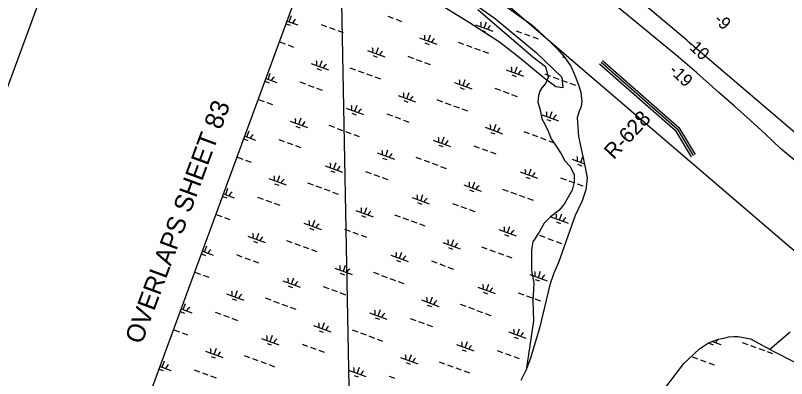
# Model space of a CAD drawing. Extents: x 3972907 to 3994831, y 172639 to 190852.
# Drawn here: x 3977932 to 3980022, y 187328 to 188313 of the extents above; entities that cross this region are included whole.
import ezdxf

# ---------------------------------------------------------------- set-up
doc = ezdxf.new("R2010")
doc.units = 0
for name, color, linetype in [('V-ANNO-SYMB', 7, 'Continuous'), ('V-ANNO-TEXT', 7, 'Continuous'), ('V-GRID-FRAM', 7, 'Continuous'), ('V-GRID-MAJR', 7, 'Continuous'), ('V-RIVR-EDGE', 7, 'Continuous'), ('V-RIVR-JETY', 7, 'Continuous'), ('V-RIVR-RANG', 7, 'Continuous'), ('V-RIVR-RANG-IDEN', 7, 'Continuous'), ('V-SITE-VEGE', 7, 'Continuous'), ('V-TOPO-DPTH', 7, 'Continuous'), ('V-TOPO-MINR', 7, 'Continuous'), ('V-WETL-SWMP', 7, 'Continuous')]:
    doc.layers.add(name, color=color, linetype=linetype)

msp = doc.modelspace()

# ---------------------------------------------------------------- linework, layer by layer
at = {"layer": 'V-ANNO-SYMB'}
msp.add_lwpolyline([(3974579.2, 179056.1), (3990105.3, 173349.5), (3994058.3, 184104.4), (3978532.2, 189811), (3974579.2, 179056.1)], dxfattribs=at)
at = {"layer": 'V-GRID-FRAM'}
msp.add_lwpolyline([(3976065.4, 181215.5), (3978987, 189164.4), (3993292.9, 183906.2), (3990371.3, 175957.4), (3976065.4, 181215.5)], dxfattribs=at)
at = {"layer": 'V-GRID-MAJR'}
msp.add_spline([(3978982.9, 179660), (3978930.1, 182429.9), (3978814.7, 188489.8), (3978791.3, 189715.7)], degree=3, dxfattribs=at)
at = {"layer": 'V-RIVR-EDGE'}
for points in [[(3979185.5, 188329.4), (3979205.2, 188311.9), (3979335.1, 188200.5), (3979369, 188174.3), (3979376.6, 188144.8), (3979369, 188128.4), (3979359.1, 188116.4), (3979353.7, 188107.7), (3979350.4, 188095.7), (3979348.2, 188078.2), (3979354.8, 188057.5), (3979359.1, 188032.3), (3979367.9, 188016), (3979376.6, 187999.6), (3979384.3, 187978.8), (3979399.6, 187955.9), (3979411.6, 187937.3), (3979421.4, 187918.8), (3979435.6, 187903.5), (3979446.5, 187880.5), (3979446.5, 187860.9), (3979441.1, 187839), (3979419.2, 187800.8), (3979405, 187784.4), (3979382.1, 187766.9), (3979365.7, 187749.5), (3979351.5, 187725.4), (3979335.1, 187699.2), (3979330.8, 187677.4), (3979330.8, 187621.7), (3979337.3, 187586.7), (3979335.1, 187538.7), (3979336.2, 187485.2), (3979316.2, 187350.6)], [(3979977.1, 187407.6), (3980031.9, 187455.1)]]:
    msp.add_lwpolyline(points, dxfattribs=at)
at = {"layer": 'V-RIVR-JETY'}
for points in [[(3979523.8, 188191.1), (3979730.4, 188009.6), (3979774.3, 187936)], [(3979515.5, 188181.7), (3979720.6, 188001.5), (3979763.5, 187929.6)], [(3979519.6, 188186.4), (3979725.5, 188005.6), (3979768.9, 187932.8)]]:
    msp.add_lwpolyline(points, dxfattribs=at)
msp.add_spline([(3979098.2, 189603), (3979284.7, 189431.5), (3979614.8, 189124.3), (3979920, 188846.7), (3980228.2, 188557.9), (3980477.4, 188312.8), (3980532, 188268.2), (3980570.9, 188243.1), (3980628.8, 188186.6), (3980663.7, 188142.5)], degree=3, dxfattribs=at)
at = {"layer": 'V-SITE-VEGE'}
for p, q in [((3979149.6, 188364.2), (3979233.9, 188303.6)), ((3979162.7, 188293), (3979073.2, 188348.4)), ((3979244.4, 188240.3), (3979162.7, 188293)), ((3979233.9, 188303.6), (3979344.5, 188211.3)), ((3979302.3, 188195.5), (3979244.4, 188240.3)), ((3979344.5, 188211.3), (3979413, 188145.4)), ((3979365.5, 188142.8), (3979302.3, 188195.5)), ((3979397.2, 188119.1), (3979365.5, 188142.8)), ((3979413, 188145.4), (3979415.6, 188116.5)), ((3979415.6, 188116.5), (3979397.2, 188119.1))]:
    msp.add_line(p, q, dxfattribs=at)
at = {"layer": 'V-TOPO-DPTH'}
for points in [[(3980186.5, 187874.7), (3979782.7, 188218.5), (3979779.2, 188221.6), (3979778, 188222.6), (3979770.9, 188228.8), (3979766.2, 188233), (3979761.5, 188237.2), (3979756.8, 188241.4), (3979752.2, 188245.7), (3979157.5, 188744)], [(3978990.6, 188578.5), (3980546.8, 187243.1), (3981084.2, 186920)]]:
    msp.add_lwpolyline(points, dxfattribs=at)
at = {"layer": 'V-TOPO-MINR'}
for points in [[(3980186.5, 187874.7), (3979782.7, 188218.5), (3979779.2, 188221.6), (3979778, 188222.6), (3979770.9, 188228.8), (3979766.2, 188233), (3979761.5, 188237.2), (3979756.8, 188241.4), (3979752.2, 188245.7), (3979157.5, 188744)], [(3980399.4, 187625), (3980006.3, 187952.1), (3979965, 187990.7), (3979923.4, 188029), (3979881.4, 188066.9), (3979839.2, 188104.5), (3979779.4, 188157.2), (3979766.8, 188168.2), (3979754.1, 188179.2), (3979741.4, 188190), (3979728.5, 188200.7), (3979422.8, 188453.3)]]:
    msp.add_lwpolyline(points, dxfattribs=at)
at = {"layer": 'V-WETL-SWMP'}
for p, q in [((3979255.7, 188341.9), (3979310.5, 188303.1)), ((3978668.6, 188297.9), (3978697.8, 188287.2)), ((3978674.3, 188295.8), (3978680.5, 188312.7)), ((3978941.5, 188310.9), (3978956.5, 188305.4)), ((3978964, 188302.6), (3978979, 188297.1)), ((3979202.8, 188278.8), (3979209, 188295.7)), ((3979310.5, 188303.1), (3979331.9, 188287.5)), ((3978666, 188290.7), (3978677.3, 188286.5)), ((3978760.7, 188288.8), (3978775.8, 188283.3)), ((3978783.3, 188280.5), (3978798.3, 188275)), ((3978805.8, 188272.2), (3978820.8, 188266.7)), ((3979179.3, 188287.4), (3979226.3, 188270.2)), ((3979194.5, 188273.6), (3979205.8, 188269.5)), ((3979331.9, 188287.5), (3979349.2, 188272.4)), ((3979349.2, 188272.4), (3979366.5, 188256)), ((3979027.2, 188252.4), (3979074.1, 188235.1)), ((3979050.6, 188243.7), (3979056.9, 188260.6)), ((3979289.2, 188271.8), (3979304.2, 188266.3)), ((3979311.7, 188263.5), (3979326.8, 188258)), ((3979334.3, 188255.2), (3979349.3, 188249.7)), ((3979366.5, 188256), (3979382.5, 188240.5)), ((3978648.5, 188241.3), (3978663.5, 188235.8)), ((3978671.1, 188233.1), (3978686.1, 188227.5)), ((3979042.4, 188238.6), (3979053.6, 188234.4)), ((3979132, 188240.9), (3979147, 188235.4)), ((3979154.5, 188232.6), (3979169.5, 188227.1)), ((3979382.5, 188240.5), (3979401.4, 188221.2)), ((3978886.4, 188217.9), (3978933.3, 188200.6)), ((3978909.9, 188209.3), (3978916.1, 188226.1)), ((3979177, 188224.3), (3979192, 188218.8)), ((3979199.5, 188216), (3979214.5, 188210.5)), ((3979401.4, 188221.2), (3979420.3, 188199.8)), ((3978757.7, 188174.2), (3978763.9, 188191.1)), ((3978901.6, 188204.1), (3978912.8, 188199.9)), ((3978996.3, 188202.2), (3979011.3, 188196.7)), ((3979018.8, 188193.9), (3979033.8, 188188.4)), ((3979414.9, 188200.9), (3979421.1, 188198.6)), ((3979420.3, 188199.8), (3979437.4, 188175.5)), ((3978734.3, 188182.8), (3978781.2, 188165.6)), ((3978749.4, 188169), (3978760.7, 188164.9)), ((3978839, 188171.3), (3978854, 188165.8)), ((3979041.3, 188185.7), (3979056.4, 188180.1)), ((3979286.2, 188157.2), (3979292.4, 188174.1)), ((3979437.4, 188175.5), (3979450.4, 188146.3)), ((3978616.9, 188139.7), (3978623.2, 188156.6)), ((3978861.5, 188163.1), (3978876.6, 188157.5)), ((3978884.1, 188154.8), (3978899.1, 188149.3)), ((3978906.6, 188146.5), (3978921.6, 188141)), ((3979262.7, 188165.8), (3979309.7, 188148.5)), ((3979277.9, 188152), (3979289.2, 188147.8)), ((3979367.5, 188154.3), (3979382.5, 188148.8)), ((3978608.6, 188134.5), (3978619.9, 188130.4)), ((3978611.2, 188141.8), (3978640.4, 188131.1)), ((3978703.4, 188132.7), (3978718.4, 188127.2)), ((3979122, 188131.3), (3979168.9, 188114.1)), ((3979145.4, 188122.7), (3979151.6, 188139.6)), ((3979390, 188146), (3979405, 188140.5)), ((3979412.6, 188137.7), (3979427.6, 188132.2)), ((3979435.1, 188129.5), (3979450.1, 188123.9)), ((3979450.4, 188146.3), (3979460.1, 188119.6)), ((3978725.9, 188124.4), (3978740.9, 188118.9)), ((3978748.4, 188116.1), (3978763.4, 188110.6)), ((3979137.1, 188117.5), (3979148.4, 188113.4)), ((3979231.8, 188115.6), (3979246.9, 188110.1)), ((3979254.4, 188107.4), (3979269.4, 188101.8)), ((3979460.1, 188119.6), (3979464.9, 188104.2)), ((3978591.1, 188085.2), (3978606.2, 188079.7)), ((3978969.8, 188096.2), (3979016.7, 188079)), ((3978993.3, 188087.6), (3978999.5, 188104.5)), ((3979074.6, 188084.8), (3979089.6, 188079.2)), ((3979276.9, 188099.1), (3979291.9, 188093.6)), ((3979464.9, 188104.2), (3979467.5, 188080.1)), ((3978613.7, 188076.9), (3978628.7, 188071.4)), ((3978852.5, 188053.1), (3978858.7, 188070)), ((3978985, 188082.4), (3978996.2, 188078.3)), ((3979097.1, 188076.5), (3979112.1, 188071)), ((3979119.6, 188068.2), (3979134.6, 188062.7)), ((3979465.3, 188066), (3979459.3, 188050.7)), ((3979467.5, 188080.1), (3979465.3, 188066)), ((3978829, 188061.8), (3978876, 188044.5)), ((3978844.2, 188048), (3978855.5, 188043.8)), ((3978938.9, 188046.1), (3978953.9, 188040.6)), ((3979142.1, 188059.9), (3979157.2, 188054.4)), ((3979357.5, 188044.7), (3979404.4, 188027.5)), ((3979381, 188036.1), (3979387.2, 188053)), ((3979459.3, 188050.7), (3979455, 188035.8)), ((3978676.9, 188026.7), (3978723.8, 188009.4)), ((3978700.3, 188018.1), (3978706.5, 188035)), ((3978961.4, 188037.8), (3978976.4, 188032.3)), ((3978984, 188029.5), (3978999, 188024)), ((3979372.7, 188030.9), (3979383.9, 188026.8)), ((3979455, 188035.8), (3979458.6, 187985.1)), ((3978559.6, 187983.6), (3978565.8, 188000.5)), ((3978692, 188012.9), (3978703.3, 188008.7)), ((3978781.6, 188015.2), (3978796.7, 188009.7)), ((3978804.2, 188006.9), (3978819.2, 188001.4)), ((3979205.3, 188009.7), (3979252.3, 187992.4)), ((3979228.8, 188001), (3979235, 188017.9)), ((3978553.8, 187985.7), (3978583, 187975)), ((3978826.7, 187998.6), (3978841.7, 187993.1)), ((3978849.2, 187990.4), (3978864.2, 187984.8)), ((3979088, 187966.6), (3979094.2, 187983.4)), ((3979220.5, 187995.9), (3979231.8, 187991.7)), ((3979310.1, 187998.2), (3979325.1, 187992.7)), ((3979332.6, 187989.9), (3979347.7, 187984.4)), ((3979355.2, 187981.6), (3979370.2, 187976.1)), ((3979458.6, 187985.1), (3979474.8, 187909.4)), ((3978551.3, 187978.4), (3978562.5, 187974.3)), ((3978646, 187976.5), (3978661, 187971)), ((3978668.5, 187968.3), (3978683.5, 187962.7)), ((3978691, 187960), (3978706, 187954.5)), ((3979064.6, 187975.2), (3979111.5, 187957.9)), ((3979079.7, 187961.4), (3979091, 187957.2)), ((3979174.4, 187959.5), (3979189.5, 187954)), ((3979377.7, 187973.3), (3979392.7, 187967.8)), ((3978912.4, 187940.1), (3978959.3, 187922.9)), ((3978935.9, 187931.5), (3978942.1, 187948.4)), ((3979197, 187951.2), (3979212, 187945.7)), ((3979219.5, 187943), (3979234.5, 187937.4)), ((3978533.8, 187929.1), (3978548.8, 187923.6)), ((3978556.3, 187920.8), (3978571.3, 187915.3)), ((3978927.6, 187926.3), (3978938.8, 187922.2)), ((3979017.2, 187928.6), (3979032.2, 187923.1)), ((3979039.7, 187920.4), (3979054.7, 187914.8)), ((3979440.9, 187923.1), (3979474.5, 187910.7)), ((3979464.4, 187914.5), (3979470.3, 187930.5)), ((3978771.6, 187905.6), (3978818.6, 187888.4)), ((3978795.1, 187897), (3978801.3, 187913.9)), ((3979062.2, 187912.1), (3979077.3, 187906.6)), ((3979084.8, 187903.8), (3979099.8, 187898.3)), ((3979323.6, 187880), (3979329.8, 187896.9)), ((3979456.1, 187909.3), (3979467.3, 187905.1)), ((3979474.8, 187909.4), (3979482.3, 187872.3)), ((3978642.9, 187861.9), (3978649.2, 187878.8)), ((3978786.8, 187891.8), (3978798.1, 187887.7)), ((3978881.5, 187890), (3978896.5, 187884.5)), ((3978904, 187881.7), (3978919.1, 187876.2)), ((3979300.1, 187888.6), (3979347, 187871.4)), ((3979315.3, 187874.8), (3979326.6, 187870.7)), ((3978619.5, 187870.6), (3978666.4, 187853.3)), ((3978634.7, 187856.8), (3978645.9, 187852.6)), ((3978724.3, 187859.1), (3978739.3, 187853.6)), ((3978926.6, 187873.4), (3978941.6, 187867.9)), ((3979171.4, 187844.9), (3979177.6, 187861.8)), ((3979410, 187872.9), (3979425, 187867.4)), ((3979432.5, 187864.7), (3979447.5, 187859.1)), ((3979455, 187856.4), (3979470.1, 187850.9)), ((3979482.3, 187872.3), (3979478.6, 187840.4)), ((3978502.2, 187827.4), (3978508.4, 187844.3)), ((3978746.8, 187850.8), (3978761.8, 187845.3)), ((3978769.3, 187842.5), (3978784.3, 187837)), ((3978791.8, 187834.2), (3978806.8, 187828.7)), ((3979148, 187853.5), (3979194.9, 187836.3)), ((3979163.1, 187839.7), (3979174.4, 187835.6)), ((3979252.7, 187842.1), (3979267.7, 187836.5)), ((3979275.3, 187833.8), (3979290.3, 187828.3)), ((3979478.6, 187840.4), (3979468.3, 187810.2)), ((3978493.9, 187822.3), (3978505.1, 187818.1)), ((3978496.4, 187829.6), (3978525.6, 187818.8)), ((3978588.6, 187820.4), (3978603.6, 187814.9)), ((3978611.1, 187812.1), (3978626.1, 187806.6)), ((3979007.2, 187819), (3979054.1, 187801.8)), ((3979030.7, 187810.4), (3979036.9, 187827.3)), ((3979297.8, 187825.5), (3979312.8, 187820)), ((3979320.3, 187817.2), (3979335.3, 187811.7)), ((3978633.6, 187803.9), (3978648.7, 187798.3)), ((3978878.5, 187775.4), (3978884.7, 187792.3)), ((3979022.4, 187805.3), (3979033.6, 187801.1)), ((3979117.1, 187803.4), (3979132.1, 187797.9)), ((3979139.6, 187795.1), (3979154.6, 187789.6)), ((3979468.3, 187810.2), (3979449.2, 187770.6)), ((3978476.4, 187773), (3978491.4, 187767.5)), ((3978855, 187784), (3978902, 187766.7)), ((3978870.2, 187770.2), (3978881.5, 187766)), ((3978959.8, 187772.5), (3978974.8, 187767)), ((3979162.1, 187786.8), (3979177.1, 187781.3)), ((3979449.2, 187770.6), (3979403.8, 187643.2)), ((3979407, 187758.3), (3979413.2, 187775.2)), ((3978498.9, 187764.7), (3978513.9, 187759.2)), ((3978714.3, 187749.5), (3978761.2, 187732.2)), ((3978737.7, 187740.9), (3978743.9, 187757.8)), ((3978982.3, 187764.2), (3978997.3, 187758.7)), ((3979004.9, 187755.9), (3979019.9, 187750.4)), ((3979383.5, 187767), (3979430.4, 187749.7)), ((3979398.7, 187753.2), (3979409.9, 187749)), ((3978729.4, 187735.7), (3978740.7, 187731.6)), ((3978824.1, 187733.8), (3978839.2, 187728.3)), ((3979027.4, 187747.7), (3979042.4, 187742.1)), ((3979242.7, 187732.5), (3979289.7, 187715.2)), ((3979266.2, 187723.8), (3979272.4, 187740.7)), ((3978562.1, 187714.4), (3978609, 187697.2)), ((3978585.6, 187705.8), (3978591.8, 187722.7)), ((3978846.7, 187725.6), (3978861.7, 187720)), ((3978869.2, 187717.3), (3978884.2, 187711.8)), ((3979257.9, 187718.7), (3979269.2, 187714.5)), ((3979352.6, 187716.8), (3979367.6, 187711.3)), ((3979375.1, 187708.5), (3979390.2, 187703)), ((3978444.8, 187671.3), (3978451, 187688.2)), ((3978577.3, 187700.6), (3978588.5, 187696.5)), ((3978666.9, 187703), (3978681.9, 187697.4)), ((3978689.4, 187694.7), (3978704.4, 187689.2)), ((3979090.6, 187697.4), (3979137.5, 187680.2)), ((3979114, 187688.8), (3979120.3, 187705.7)), ((3979397.7, 187700.3), (3979412.7, 187694.7)), ((3978436.5, 187666.2), (3978447.8, 187662)), ((3978439, 187673.4), (3978468.3, 187662.7)), ((3978711.9, 187686.4), (3978726.9, 187680.9)), ((3978734.4, 187678.1), (3978749.5, 187672.6)), ((3978973.3, 187654.3), (3978979.5, 187671.2)), ((3979105.7, 187683.6), (3979117, 187679.5)), ((3979195.3, 187685.9), (3979210.4, 187680.4)), ((3979217.9, 187677.6), (3979232.9, 187672.1)), ((3979240.4, 187669.4), (3979255.4, 187663.9)), ((3978531.2, 187664.3), (3978546.2, 187658.8)), ((3978553.7, 187656), (3978568.7, 187650.5)), ((3978576.3, 187647.7), (3978591.3, 187642.2)), ((3978949.8, 187662.9), (3978996.7, 187645.7)), ((3978965, 187649.1), (3978976.2, 187645)), ((3979059.7, 187647.3), (3979074.7, 187641.8)), ((3979262.9, 187661.1), (3979277.9, 187655.6)), ((3978797.6, 187627.9), (3978844.6, 187610.6)), ((3978821.1, 187619.2), (3978827.3, 187636.1)), ((3979082.2, 187639), (3979097.2, 187633.5)), ((3979104.7, 187630.7), (3979119.8, 187625.2)), ((3979403.8, 187643.2), (3979391.8, 187613.8)), ((3978419, 187616.8), (3978434, 187611.3)), ((3978441.5, 187608.6), (3978456.5, 187603)), ((3978812.8, 187614.1), (3978824.1, 187609.9)), ((3978902.4, 187616.4), (3978917.4, 187610.9)), ((3978924.9, 187608.1), (3978940, 187602.6)), ((3979326.1, 187610.8), (3979373.1, 187593.6)), ((3979349.6, 187602.2), (3979355.8, 187619.1)), ((3979391.8, 187613.8), (3979381.1, 187582.4)), ((3978656.9, 187593.4), (3978703.8, 187576.1)), ((3978680.3, 187584.7), (3978686.5, 187601.6)), ((3978947.5, 187599.8), (3978962.5, 187594.3)), ((3978970, 187591.5), (3978985, 187586)), ((3979208.8, 187567.7), (3979215, 187584.6)), ((3979341.3, 187597), (3979352.6, 187592.9)), ((3979381.1, 187582.4), (3979365.9, 187521.5)), ((3978528.2, 187549.7), (3978534.4, 187566.6)), ((3978672, 187579.6), (3978683.3, 187575.4)), ((3978766.7, 187577.7), (3978781.8, 187572.2)), ((3978789.3, 187569.4), (3978804.3, 187563.9)), ((3979185.4, 187576.3), (3979232.3, 187559.1)), ((3979200.5, 187562.6), (3979211.8, 187558.4)), ((3978504.7, 187558.3), (3978551.6, 187541.1)), ((3978519.9, 187544.5), (3978531.1, 187540.4)), ((3978609.5, 187546.8), (3978624.5, 187541.3)), ((3978811.8, 187561.2), (3978826.8, 187555.6)), ((3979033.2, 187541.3), (3979080.1, 187524)), ((3979056.7, 187532.7), (3979062.9, 187549.6)), ((3979295.2, 187560.7), (3979310.2, 187555.2)), ((3979317.8, 187552.4), (3979332.8, 187546.9)), ((3979340.3, 187544.1), (3979355.3, 187538.6)), ((3978387.4, 187515.2), (3978393.6, 187532.1)), ((3978632, 187538.5), (3978647, 187533)), ((3978654.5, 187530.3), (3978669.6, 187524.7)), ((3978677.1, 187522), (3978692.1, 187516.5)), ((3979048.4, 187527.5), (3979059.6, 187523.3)), ((3979138, 187529.8), (3979153, 187524.3)), ((3979160.5, 187521.5), (3979175.5, 187516)), ((3979365.9, 187521.5), (3979352.8, 187465.2)), ((3978379.1, 187510), (3978390.4, 187505.9)), ((3978381.7, 187517.3), (3978410.9, 187506.6)), ((3978473.8, 187508.2), (3978488.8, 187502.7)), ((3978496.3, 187499.9), (3978511.4, 187494.4)), ((3978892.4, 187506.8), (3978939.3, 187489.5)), ((3978915.9, 187498.2), (3978922.1, 187515.1)), ((3979183, 187513.2), (3979198, 187507.7)), ((3979205.5, 187505), (3979220.6, 187499.4)), ((3978518.9, 187491.6), (3978533.9, 187486.1)), ((3978763.7, 187463.1), (3978769.9, 187480)), ((3978907.6, 187493), (3978918.9, 187488.9)), ((3979002.3, 187491.1), (3979017.3, 187485.6)), ((3979024.8, 187482.9), (3979039.8, 187477.3)), ((3978361.6, 187460.7), (3978376.6, 187455.2)), ((3978740.3, 187471.7), (3978787.2, 187454.5)), ((3978755.4, 187457.9), (3978766.7, 187453.8)), ((3978845, 187460.3), (3978860, 187454.7)), ((3979047.3, 187474.6), (3979062.4, 187469.1)), ((3979292.2, 187446.1), (3979298.4, 187463)), ((3979352.8, 187465.2), (3979327.8, 187381.2)), ((3978384.1, 187452.4), (3978399.1, 187446.9)), ((3978599.5, 187437.2), (3978646.4, 187420)), ((3978623, 187428.6), (3978629.2, 187445.5)), ((3978867.6, 187452), (3978882.6, 187446.5)), ((3978890.1, 187443.7), (3978905.1, 187438.2)), ((3979268.7, 187454.7), (3979315.7, 187437.5)), ((3979283.9, 187440.9), (3979295.2, 187436.8)), ((3978614.7, 187423.5), (3978625.9, 187419.3)), ((3978709.4, 187421.6), (3978724.4, 187416.1)), ((3978912.6, 187435.4), (3978927.6, 187429.9)), ((3979128, 187420.2), (3979174.9, 187403)), ((3979151.4, 187411.6), (3979157.6, 187428.5)), ((3979812.4, 187423.9), (3979823.7, 187419.7)), ((3979820.8, 187429), (3979844.1, 187420.4)), ((3979902, 187426.2), (3979917, 187420.7)), ((3979924.5, 187417.9), (3979939.5, 187412.4)), ((3978447.3, 187402.2), (3978494.3, 187384.9)), ((3978470.8, 187393.6), (3978477, 187410.5)), ((3978731.9, 187413.3), (3978746.9, 187407.8)), ((3978754.4, 187405), (3978769.4, 187399.5)), ((3979143.1, 187406.4), (3979154.4, 187402.3)), ((3979237.8, 187404.6), (3979252.9, 187399.1)), ((3979260.4, 187396.3), (3979275.4, 187390.8)), ((3979947, 187409.6), (3979962.1, 187404.1)), ((3979969.6, 187401.4), (3979984.6, 187395.8)), ((3978330, 187359.1), (3978336.2, 187376)), ((3978462.5, 187388.4), (3978473.8, 187384.2)), ((3978552.1, 187390.7), (3978567.1, 187385.2)), ((3978574.6, 187382.4), (3978589.6, 187376.9)), ((3978597.2, 187374.1), (3978612.2, 187368.6)), ((3978975.8, 187385.2), (3979022.7, 187367.9)), ((3978999.3, 187376.5), (3979005.5, 187393.4)), ((3979080.6, 187373.7), (3979095.6, 187368.2)), ((3979282.9, 187388), (3979297.9, 187382.5)), ((3979327.8, 187381.2), (3979315.9, 187349.8)), ((3979766.3, 187387.5), (3979781.3, 187382)), ((3979788.8, 187379.3), (3979803.9, 187373.7)), ((3978321.7, 187353.9), (3978333, 187349.8)), ((3978324.3, 187361.2), (3978353.5, 187350.4)), ((3978619.7, 187365.9), (3978634.7, 187360.3)), ((3978858.5, 187342), (3978864.7, 187358.9)), ((3978991, 187371.4), (3979002.2, 187367.2)), ((3979103.1, 187365.4), (3979118.1, 187359.9)), ((3979125.6, 187357.1), (3979140.6, 187351.6)), ((3979811.4, 187371), (3979826.4, 187365.5)), ((3978416.4, 187352), (3978431.5, 187346.5)), ((3978439, 187343.8), (3978454, 187338.2)), ((3978461.5, 187335.5), (3978476.5, 187330)), ((3978835, 187350.7), (3978882, 187333.4)), ((3978850.2, 187336.9), (3978861.5, 187332.7)), ((3978944.9, 187335), (3978959.9, 187329.5)), ((3979148.2, 187348.8), (3979163.2, 187343.3)), ((3979315.9, 187349.8), (3979301.9, 187322.5))]:
    msp.add_line(p, q, dxfattribs=at)
msp.add_lwpolyline([(3979669.6, 187271.2), (3979744.2, 187369.2), (3979786.5, 187409.1), (3979810.8, 187425), (3979822.9, 187429.8), (3979837.5, 187434.7), (3979852.1, 187438.2), (3979865.4, 187441), (3979879.1, 187442.5), (3979891.5, 187442.4), (3979924.3, 187436.2), (3979987.8, 187401.9), (3980090.6, 187348.8)], dxfattribs=at)
for centre, start, end in [((3978700.3, 188286.5), 119.0473, 160.5909), ((3979177, 188288.6), 339.0473, 20.5909), ((3979228.8, 188269.5), 119.0473, 160.5909), ((3979024.8, 188253.5), 339.0473, 20.5909), ((3979076.7, 188234.4), 119.0473, 160.5909), ((3978884, 188219), 339.0473, 20.5909), ((3978935.9, 188199.9), 119.0473, 160.5909), ((3978731.9, 188183.9), 339.0473, 20.5909), ((3978783.7, 188164.9), 119.0473, 160.5909), ((3979260.4, 188166.9), 339.0473, 20.5909), ((3979312.2, 188147.9), 119.0473, 160.5909), ((3978642.9, 188130.4), 119.0473, 160.5909), ((3979119.6, 188132.4), 339.0473, 20.5909), ((3979171.4, 188113.4), 119.0473, 160.5909), ((3978967.4, 188097.4), 339.0473, 20.5909), ((3979019.3, 188078.3), 119.0473, 160.5909), ((3978826.6, 188062.9), 339.0473, 20.5909), ((3978878.5, 188043.8), 119.0473, 160.5909), ((3979355.1, 188045.9), 339.0473, 20.5909), ((3979407, 188026.8), 119.0473, 160.5909), ((3978674.5, 188027.8), 339.0473, 20.5909), ((3978726.3, 188008.8), 119.0473, 160.5909), ((3979203, 188010.8), 339.0473, 20.5909), ((3979254.8, 187991.7), 119.0473, 160.5909), ((3978585.6, 187974.3), 119.0473, 160.5909), ((3979062.2, 187976.3), 339.0473, 20.5909), ((3979114, 187957.2), 119.0473, 160.5909), ((3978910, 187941.2), 339.0473, 20.5909), ((3978961.9, 187922.2), 119.0473, 160.5909), ((3979438.5, 187924.2), 339.0473, 20.5909), ((3978769.3, 187906.8), 339.0473, 20.5909), ((3978821.1, 187887.7), 119.0473, 160.5909), ((3979297.7, 187889.7), 339.0473, 20.5909), ((3979490.4, 187905.2), 156.5924, 160.5909), ((3978617.1, 187871.7), 339.0473, 20.5909), ((3979349.6, 187870.7), 119.0473, 160.5909), ((3978669, 187852.6), 119.0473, 160.5909), ((3979145.6, 187854.7), 339.0473, 20.5909), ((3978528.2, 187818.1), 119.0473, 160.5909), ((3979197.4, 187835.6), 119.0473, 160.5909), ((3979004.8, 187820.2), 339.0473, 20.5909), ((3979056.7, 187801.1), 119.0473, 160.5909), ((3978852.7, 187785.1), 339.0473, 20.5909), ((3978904.5, 187766.1), 119.0473, 160.5909), ((3979381.1, 187768.1), 339.0473, 20.5909), ((3978711.9, 187750.6), 339.0473, 20.5909), ((3979433, 187749), 119.0473, 160.5909), ((3978763.7, 187731.6), 119.0473, 160.5909), ((3979240.4, 187733.6), 339.0473, 20.5909), ((3979292.2, 187714.5), 119.0473, 160.5909), ((3978559.7, 187715.6), 339.0473, 20.5909), ((3978611.6, 187696.5), 119.0473, 160.5909), ((3979088.2, 187698.5), 339.0473, 20.5909), ((3979140, 187679.5), 119.0473, 160.5909), ((3978470.8, 187662), 119.0473, 160.5909), ((3978947.4, 187664.1), 339.0473, 20.5909), ((3978999.3, 187645), 119.0473, 160.5909), ((3978795.3, 187629), 339.0473, 20.5909), ((3978847.1, 187609.9), 119.0473, 160.5909), ((3979323.7, 187612), 339.0473, 20.5909), ((3979375.6, 187592.9), 119.0473, 160.5909), ((3978654.5, 187594.5), 339.0473, 20.5909), ((3978706.3, 187575.4), 119.0473, 160.5909), ((3979183, 187577.5), 339.0473, 20.5909), ((3978502.3, 187559.4), 339.0473, 20.5909), ((3979234.8, 187558.4), 119.0473, 160.5909), ((3978554.2, 187540.4), 119.0473, 160.5909), ((3979030.8, 187542.4), 339.0473, 20.5909), ((3978413.4, 187505.9), 119.0473, 160.5909), ((3979082.7, 187523.3), 119.0473, 160.5909), ((3978890, 187507.9), 339.0473, 20.5909), ((3978941.9, 187488.9), 119.0473, 160.5909), ((3978737.9, 187472.9), 339.0473, 20.5909), ((3978789.7, 187453.8), 119.0473, 160.5909), ((3979266.4, 187455.8), 339.0473, 20.5909), ((3978597.1, 187438.4), 339.0473, 20.5909), ((3979318.2, 187436.8), 119.0473, 160.5909), ((3978649, 187419.3), 119.0473, 160.5909), ((3979125.6, 187421.3), 339.0473, 20.5909), ((3979177.4, 187402.3), 119.0473, 160.5909), ((3979846.7, 187419.7), 122.9829, 160.5909), ((3978445, 187403.3), 339.0473, 20.5909), ((3978496.8, 187384.2), 119.0473, 160.5909), ((3978973.4, 187386.3), 339.0473, 20.5909), ((3979025.3, 187367.2), 119.0473, 160.5909), ((3978356, 187349.8), 119.0473, 160.5909), ((3978832.7, 187351.8), 339.0473, 20.5909), ((3978884.5, 187332.7), 119.0473, 160.5909)]:
    msp.add_arc(centre, 17.6, start, end, dxfattribs=at)

# ---------------------------------------------------------------- texts
at = {"layer": 'V-ANNO-TEXT'}
msp.add_text('OVERLAPS SHEET 83', height=50, rotation=69.7596, dxfattribs=at).set_placement((3978274.6, 187418.9))
at = {"layer": 'V-RIVR-RANG'}
for s, rotation, p in [('-9', 316.8472, (3979823.2, 188298.6)), ('-10', 316.8472, (3979746.7, 188233.3)), ('-19', 316.7083, (3979701.5, 188161))]:
    msp.add_text(s, height=33.5, rotation=rotation, dxfattribs=at).set_placement(p)
at = {"layer": 'V-RIVR-RANG-IDEN'}
msp.add_text('R-628  ', height=41.5, rotation=46.8617, dxfattribs=at).set_placement((3979553.8, 187920.5))

doc.saveas('drawing.dxf')
